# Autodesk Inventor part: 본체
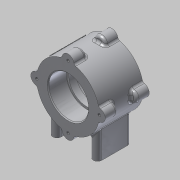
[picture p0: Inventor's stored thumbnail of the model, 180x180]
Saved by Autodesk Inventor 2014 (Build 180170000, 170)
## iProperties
Created: 2015-03
Part Number: 본체
Material: 알루미늄 6061
Document SubType Name: Modeling
Designer: MYHOME
Density: 2.71 g/cm^3
Appearance: 알루미늄 - 평지
Mass: 450.776 g
Surface Area: 332.745 cm^2
Volume: 166.338 cm^3
Author: MYHOME
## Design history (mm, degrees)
sketch "스케치2"
  geometry: C1 r 37 at (0, 0); 1 further point
  constraints: 1 centre point, 1 coincident
  dimensions: "d0" = 74 diameter of C1
extrude "돌출1" new body sketch "스케치2" stored distance "d1" = 52; taper "d2" = 0 deg
sketch "스케치3"
  geometry: C1 r 37 at (0, 0) reference; C2 r 23.5 at (0, 0)
  constraints: 1 centre point, 1 coincident
  dimensions: "d3" = 47 diameter of C2
extrude "돌출2" cut sketch "스케치3" distance "d4" = 22; taper "d5" = 0 deg
sketch "스케치4"
  geometry: C1 r 23.5 at (0, 0) reference; C2 r 7 at (0, 37); C3 r 7 at (-37, 0); C4 r 7 at (0, -37); C5 r 7 at (37, 0); A1 r 37 centre (0, 0) between (0, 37) and (-37, 0) reference
  constraints: 4 centre point, 4 point on circle, 2 horizontal alignment, 2 vertical alignment
  dimensions: "d6" = 14 diameter of C3; "d7" = 14 diameter of C4; "d8" = 14 diameter of C5; "d9" = 14 diameter of C2
extrude "돌출3" join sketch "스케치4" distance "d10" = 15; taper "d11" = 0 deg
sketch "스케치5"
  geometry: A1 r 37 centre (0, 0) between (36.338, 6.969) and (6.969, 36.338) reference; A2 r 7 centre (0, 37) between (6.969, 36.338) and (-6.969, 36.338) reference; A3 r 7 centre (-37, 0) between (-36.338, 6.969) and (-36.338, -6.969) reference; A4 r 7 centre (0, -37) between (-6.969, -36.338) and (6.969, -36.338) reference; A5 r 7 centre (37, 0) between (36.338, -6.969) and (36.338, 6.969) reference; 4 further points
  constraints: 4 coincident, 2 horizontal alignment, 2 vertical alignment
hole "구멍1" sketch "스케치5" at (0, 37), (0, -37), (37, 0), (-37, 0) diameter "d12" = 3.242; stored, may be unused: countersink angle "d16" = 90 deg, drill point angle "d18" = 118 deg; dims "d13" = 8, "d14" = 4, "d15" = 2, "d17" = 11
sketch "스케치6"
  geometry: C1 r 23.5 at (0, 0) reference; C2 r 21 at (0, 0)
  constraints: 1 centre point, 1 coincident
  dimensions: "d19" = 42 diameter of C2
extrude "돌출4" cut sketch "스케치6" distance "d20" = 8; taper "d21" = 0 deg
sketch "스케치7"
  geometry: L1 (-29, -22.978)-(-29, -56); L2 (-29, -56)-(-19, -56); L3 (-19, -56)-(-19, -31.749); A1 r 37 centre (0, 0) between (-36.338, -6.969) and (-6.969, -36.338) reference; 1 further point
  constraints: 6 end point, 2 point on circle, 1 parallel, 1 perpendicular, 1 vertical
  dimensions: "d22" = 56 distance from line of L2 point (0, 0); "d23" = 29 distance from line of L1 point (0, 0); "d24" = 10 distance of L1.end L2.end
extrude "돌출5" join sketch "스케치7" stored distance "d25" = 40; taper "d26" = 0 deg
sketch "스케치8"
  geometry: L1 (10, 0)-(10, -40) reference; L2 (0, 0)-(10, 0) reference; L3 (10, -40)-(0, -40) reference; 3 further points
  dimensions: "d27" = 5 distance from line of L1 point (5, -5); "d28" = 5 distance from line of L1 point (5, -35); "d29" = 5 distance from line of L3 point (5, -35); "d30" = 5 distance from line of L2 point (5, -5)
hole "구멍2" sketch "스케치8" at (5, -5), (5, -35) diameter "d31" = 4.134; stored, may be unused: countersink angle "d35" = 90 deg, drill point angle "d37" = 118 deg; dims "d32" = 6, "d33" = 4, "d34" = 2, "d36" = 8
sketch "스케치9"
  geometry: L1 (0, 0)-(0, 37); L2 (0, 0)-(26.163, 26.163); A1 r 37 centre (0, 0) between (36.338, 6.969) and (6.969, 36.338) reference; 2 further points
  constraints: 4 end point, 2 point on circle, 1 coincident, 1 vertical
  dimensions: "d38" = 45 deg angle of L2 L1
node "작업 평면1"
sketch "스케치10"
  geometry: L1 (-26, 20.767)-(-26, -20.767) reference; 2 further points
  constraints: 1 coincident, 1 other
  dimensions: "d39" = 26 distance from line of L1 point (0, 0)
feature "엠보싱1" sketch "스케치10" dims "d40" = 0.5, "d41" = 0
chamfer "모따기1" distance "d42" = 1; stored, may be unused: second distance "d43" = 2, angle "d44" = 45 deg
fillet "모깎기1" dims "d45" = 5
fillet "모깎기2" dims "d46" = 3
fillet "모깎기3" dims "d47" = 3
fillet "모깎기4" dims "d48" = 3
fillet "모깎기5" dims "d49" = 0.3
node "솔리드1"
mirror "대칭1"
mirror "대칭2"
